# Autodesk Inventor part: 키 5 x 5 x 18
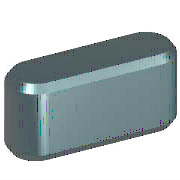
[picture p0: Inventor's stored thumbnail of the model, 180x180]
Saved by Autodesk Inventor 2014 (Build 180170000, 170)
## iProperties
Created: 2012-02
Part Number: 키 5 x 5 x 18
Material: 강철, 연강
Description: 키 및 해당 키홈
Document SubType Name: Modeling
Standard: KS B 1311
Designer: mduedu
Standards Organization: KS
Language: ko-KR
Size Designation: 5 x 5 x 18
Categories: <MemberInstance><Categories><Category DisplayName="샤프트 부품" InternalName="7f7aeb1f-a693-4053-b835-cee3144e0d98" Mnemonic="SHFT"><Category DisplayName="키" Interna
Density: 7.86 g/cm^3
Mass: 3.27476 g
Surface Area: 3.57848 cm^2
Volume: 0.416636 cm^3
Appearance: 매끄러움 - 노란색
IsCustomPart: 1
Author: mduedu
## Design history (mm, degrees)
workplane "Work Plane1"
workplane "Work Plane2"
sketch "스케치1"
  geometry: L1 (2.5, 2.5)-(15.5, 2.5); L2 (15.5, -2.5)-(2.5, -2.5); L3 (0, 8.9)-(0, -4.4) reference; L4 (-4, 0)-(24, 0) reference; L5 (18, 0)-(18, 7); A1 r 2.5 centre (2.5, 0) between (2.5, 2.5) and (2.5, -2.5); A2 r 2.5 centre (15.5, 0) between (15.5, -2.5) and (15.5, 2.5)
  constraints: 6 end point, 5 point on circle, 4 tangent, 3 point on line, 2 centre point, 1 horizontal, 1 parallel, 1 perpendicular
  dimensions: "d0" = 2.5 radius of A1 (= 0.5 x PB); "d13" = 2.5 radius of A2 (= 0.5 x PB); "d14" = 18 distance between parallel lines of L5 L3 (= NLG)
extrude "본체1" new body sketch "스케치1" taper "d3" = 0 deg; stored distance "d4" = 10
workplane "Work Plane3"
body "Solid1"
chamfer "모따기1" distance "d8" = 0.4 (= PHH); stored, may be unused: second distance "d9" = 0.4 (= PHH), angle "d15" = 45 deg
other parameters: "d1" = -3 (= -PNT), "d2" = 2 (= PH - PNT), "NLG" = 18 [user parameter; used in 3 equation terms], "PB" = 5 [user parameter; used in 2 equation terms], "PNT" = 3 [user parameter; used in 2 equation terms], "PH" = 5 [user parameter; used in 1 equation term], "PHH" = 0.4 [user parameter; used in 2 equation terms], "d10" = 0, "d16" = 0, "d17" = 0, "d18" = 0, "WDMIN" = 12 [user parameter], "PLB2" = 18 (= NLG) [user parameter], "WDMAX" = 17 [user parameter], "PLB1" = 18 (= NLG) [user parameter], "RR" = 0.16 [user parameter], "PUEB" = 2.3 [user parameter]
